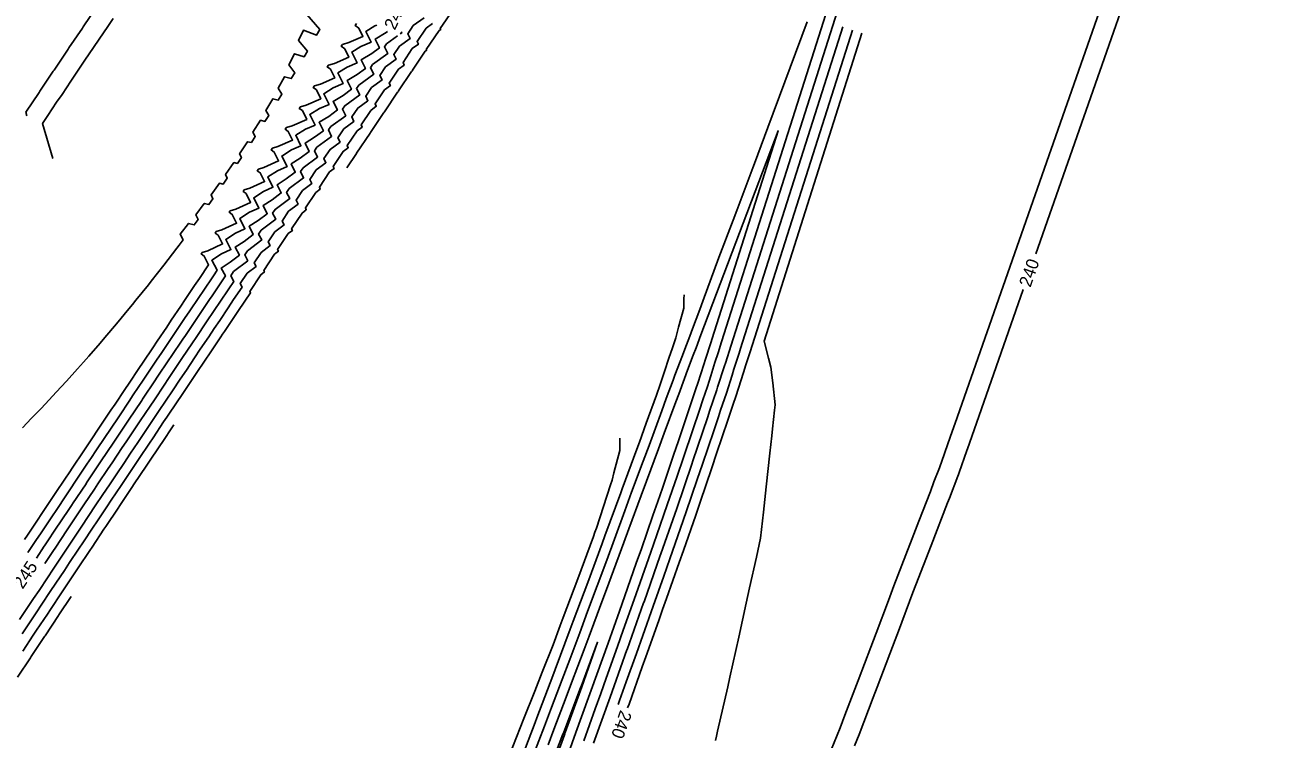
# Model space of a CAD drawing. Extents: x 1160447 to 1162032, y 616022 to 618272.
# Drawn here: x 1160773.9 to 1161021.2, y 616418.1 to 616560 of the extents above; entities that cross this region are included whole.
import ezdxf

# ---------------------------------------------------------------- set-up
doc = ezdxf.new("R2010")
doc.units = 0
doc.layers.add('D_Contours_Major', color=7, linetype='Continuous')
doc.layers.add('D_Contours_Minor', color=7, linetype='Continuous')

msp = doc.modelspace()

# ---------------------------------------------------------------- linework, layer by layer
at = {"layer": 'D_Contours_Major'}
for points in [[(1160974.68, 616514.45), (1161006.96, 616606.59), (1161007.29, 616607.53), (1161007.74, 616608.8), (1161010.59, 616616.88), (1161011.09, 616618.29), (1161013.25, 616624.34), (1161013.42, 616624.81), (1161013.92, 616626.21), (1161014.8, 616628.63), (1161017.28, 616635.52), (1161017.6, 616638.61), (1161019.75, 616644.29), (1161020.92, 616644.74), (1161021.22, 616647.76), (1161021.25, 616647.83)], [(1160893.59, 616424.24), (1160893.88, 616425.02), (1160896.51, 616432.4), (1160897.23, 616434.4), (1160899.8, 616441.64), (1160900.56, 616443.78), (1160901.33, 616445.98), (1160903.86, 616453.16), (1160904.68, 616455.52), (1160907.14, 616462.56), (1160908.01, 616465.1), (1160910.34, 616471.98), (1160911.29, 616474.8), (1160913.52, 616481.41), (1160914.59, 616484.59), (1160915.1, 616486.13), (1160915.62, 616487.76), (1160916.62, 616490.87), (1160917.11, 616492.4), (1160917.93, 616494.99), (1160938.26, 616558.94)], [(1160776.14, 616454.03), (1160777.71, 616456.4), (1160777.75, 616456.45), (1160780.47, 616460.54), (1160780.53, 616460.62), (1160783.23, 616464.67), (1160783.31, 616464.79), (1160786, 616468.8), (1160786.1, 616468.95), (1160788.76, 616472.94), (1160788.88, 616473.12), (1160791.52, 616477.07), (1160791.66, 616477.28), (1160794.29, 616481.2), (1160794.45, 616481.44), (1160797.06, 616485.33), (1160797.24, 616485.59), (1160799.83, 616489.46), (1160800.02, 616489.75), (1160802.6, 616493.59), (1160802.81, 616493.9), (1160805.37, 616497.71), (1160805.6, 616498.06), (1160808.14, 616501.84), (1160810.66, 616505.59), (1160810.91, 616505.96), (1160813.43, 616509.71), (1160813.69, 616510.09), (1160812.87, 616511.65), (1160814.66, 616512.82), (1160816.46, 616514.21), (1160815.65, 616515.8), (1160817.42, 616516.94), (1160819.24, 616518.33), (1160818.42, 616519.94), (1160820.19, 616521.07), (1160822.02, 616522.45), (1160821.2, 616524.08), (1160822.97, 616525.2), (1160824.8, 616526.57), (1160823.98, 616528.21), (1160825.77, 616529.34), (1160827.58, 616530.69), (1160826.76, 616532.35), (1160828.57, 616533.49), (1160830.36, 616534.81), (1160829.54, 616536.48), (1160831.39, 616537.64), (1160833.15, 616538.93), (1160832.32, 616540.62), (1160834.22, 616541.79), (1160835.93, 616543.05), (1160835.1, 616544.75), (1160837.06, 616545.95), (1160838.72, 616547.16), (1160837.88, 616548.88), (1160839.9, 616550.12), (1160841.51, 616551.28), (1160840.66, 616553), (1160842.76, 616554.29), (1160844.3, 616555.39), (1160843.45, 616557.13), (1160845.63, 616558.46), (1160845.92, 616558.67)], [(1160972.21, 616507.4), (1160962.44, 616479.52), (1160961.12, 616475.75), (1160960.99, 616475.39), (1160959.45, 616471.02), (1160959.32, 616470.65), (1160959.18, 616470.27), (1160957.53, 616465.95), (1160957.16, 616465), (1160953.91, 616456.55), (1160950.87, 616448.69), (1160950.28, 616447.17), (1160947.39, 616439.49), (1160946.74, 616437.75), (1160943.91, 616430.26), (1160943.18, 616428.34), (1160942.42, 616426.34), (1160939.6, 616418.94), (1160938.67, 616416.69)], [(1160772.37, 616430.33), (1160774.94, 616434.21), (1160775.11, 616434.46), (1160777.75, 616438.42), (1160777.86, 616438.59), (1160780.56, 616442.64), (1160780.61, 616442.72), (1160783.04, 616446.37)], [(1160877.31, 616409.96), (1160880.76, 616419.03), (1160880.85, 616419.24), (1160884.32, 616428.43), (1160884.35, 616428.53), (1160887.64, 616437.29), (1160884.49, 616428.47), (1160881.21, 616419.36), (1160881.13, 616419.13), (1160881.04, 616418.9), (1160877.74, 616409.8)]]:
    msp.add_lwpolyline(points, dxfattribs=at)
at = {"layer": 'D_Contours_Minor'}
for points in [[(1160886.82, 616417.23), (1160890.12, 616426.4), (1160890.92, 616428.63), (1160893.47, 616435.77), (1160893.5, 616435.86), (1160896.79, 616445.14), (1160896.87, 616445.35), (1160900.1, 616454.52), (1160900.21, 616454.85), (1160903.38, 616463.9), (1160906.35, 616472.66), (1160906.57, 616473.32), (1160909.46, 616481.87), (1160909.75, 616482.74), (1160909.9, 616483.19), (1160911.33, 616487.45), (1160911.49, 616487.97), (1160912.84, 616492.19), (1160913.02, 616492.75), (1160914.15, 616496.3), (1160954.95, 616624.67)], [(1160884.88, 616417.74), (1160887.16, 616424.08), (1160888.25, 616427.09), (1160889.35, 616430.19), (1160891.59, 616436.45), (1160892.73, 616439.68), (1160894.91, 616445.82), (1160896.09, 616449.17), (1160898.21, 616455.19), (1160899.43, 616458.67), (1160901.49, 616464.57), (1160903.43, 616470.29), (1160904.69, 616473.98), (1160906.55, 616479.5), (1160907.86, 616483.4), (1160908.54, 616485.43), (1160909.44, 616488.11), (1160910.12, 616490.22), (1160910.95, 616492.85), (1160911.57, 616494.78), (1160912.26, 616496.96), (1160947.99, 616609.37)], [(1160932.83, 616413.03), (1160935.84, 616420.31), (1160936.78, 616422.79), (1160939.42, 616429.7), (1160941.94, 616436.35), (1160942.98, 616439.1), (1160945.41, 616445.57), (1160946.51, 616448.51), (1160948.9, 616454.68), (1160950.14, 616457.89), (1160951.47, 616461.34), (1160953.75, 616467.27), (1160954.47, 616469.14), (1160955.55, 616471.97), (1160956.53, 616474.77), (1160957.22, 616476.71), (1160958.07, 616479.15), (1160958.66, 616480.83), (1161003.19, 616607.91)], [(1160853.17, 616561.34), (1160851.02, 616559.81), (1160849.92, 616558.18), (1160850.38, 616557.24), (1160848.26, 616555.71), (1160847.14, 616554.05), (1160847.6, 616553.13), (1160845.51, 616551.62), (1160844.36, 616549.92), (1160844.81, 616549.02), (1160842.75, 616547.53), (1160841.59, 616545.79), (1160842.02, 616544.9), (1160839.99, 616543.43), (1160838.81, 616541.67), (1160839.24, 616540.79), (1160837.24, 616539.33), (1160836.04, 616537.53), (1160836.46, 616536.68), (1160834.49, 616535.23), (1160833.26, 616533.4), (1160833.67, 616532.57), (1160831.74, 616531.14), (1160830.49, 616529.26), (1160830.89, 616528.45), (1160829, 616527.04), (1160827.72, 616525.12), (1160828.12, 616524.34), (1160826.25, 616522.94), (1160824.95, 616520.98), (1160825.34, 616520.22), (1160823.51, 616518.84), (1160822.18, 616516.84), (1160822.56, 616516.1), (1160820.77, 616514.73), (1160819.42, 616512.7), (1160819.79, 616511.98), (1160818.03, 616510.63), (1160816.65, 616508.56), (1160817.01, 616507.86), (1160815.33, 616505.37), (1160814.24, 616503.74), (1160812.56, 616501.24), (1160811.47, 616499.62), (1160810.38, 616497.99), (1160808.7, 616495.5), (1160807.55, 616493.79), (1160805.93, 616491.38), (1160804.73, 616489.59), (1160803.17, 616487.25), (1160801.91, 616485.39), (1160800.4, 616483.13), (1160799.1, 616481.19), (1160797.63, 616479), (1160796.29, 616476.99), (1160794.87, 616474.88), (1160793.48, 616472.8), (1160792.11, 616470.75), (1160790.67, 616468.59), (1160789.35, 616466.62), (1160787.85, 616464.38), (1160786.59, 616462.49), (1160785.05, 616460.18), (1160783.83, 616458.36), (1160782.25, 616455.99), (1160781.07, 616454.23), (1160779.45, 616451.8), (1160778.32, 616450.1), (1160776.66, 616447.61), (1160775.56, 616445.96), (1160773.87, 616443.42), (1160772.81, 616441.83)], [(1160773.35, 616479.88), (1160775.2, 616481.79), (1160777.08, 616483.77), (1160778.68, 616485.47), (1160780.1, 616487.01), (1160782.11, 616489.19), (1160784.29, 616491.62), (1160785.48, 616492.95), (1160786.54, 616494.17), (1160788.79, 616496.74), (1160789.71, 616497.82), (1160792.05, 616500.56), (1160794.51, 616503.54), (1160795.25, 616504.42), (1160795.92, 616505.26), (1160798.39, 616508.32), (1160798.97, 616509.06), (1160801.48, 616512.25), (1160804.05, 616515.62), (1160804.51, 616516.22), (1160805.3, 616517.28), (1160804.68, 616518.36), (1160806.37, 616520.51), (1160807.49, 616520.22), (1160808.28, 616521.32), (1160807.79, 616522.24), (1160809.48, 616524.49), (1160810.41, 616524.26), (1160811.21, 616525.39), (1160810.84, 616526.17), (1160812.5, 616528.5), (1160813.28, 616528.34), (1160814.07, 616529.5), (1160813.74, 616530.22), (1160815.37, 616532.59), (1160816.09, 616532.45), (1160816.87, 616533.63), (1160816.52, 616534.37), (1160818.1, 616536.75), (1160818.85, 616536.6), (1160819.61, 616537.79), (1160819.17, 616538.63), (1160820.67, 616541), (1160821.55, 616540.79), (1160822.29, 616541.98), (1160821.73, 616542.95), (1160823.14, 616545.29), (1160824.2, 616545.02), (1160824.92, 616546.2), (1160824.15, 616547.4), (1160825.44, 616549.67), (1160826.79, 616549.28), (1160827.48, 616550.45), (1160826.31, 616552.05), (1160827.45, 616554.21), (1160829.33, 616553.58), (1160829.99, 616554.73), (1160828.24, 616556.89), (1160829.2, 616558.88), (1160831.81, 616557.92), (1160832.43, 616559.04), (1160829.86, 616562)], [(1160788.11, 616563.48), (1160785.44, 616559.57), (1160785.27, 616559.33), (1160782.61, 616555.4), (1160782.45, 616555.16), (1160782.29, 616554.92), (1160779.64, 616550.99), (1160779.48, 616550.74), (1160776.84, 616546.81), (1160776.67, 616546.55), (1160774.06, 616542.62), (1160774.26, 616541.91)], [(1160837.81, 616531.54), (1160839.72, 616534.4), (1160839.76, 616534.43), (1160839.75, 616534.45), (1160842.44, 616538.47), (1160842.54, 616538.54), (1160842.52, 616538.58), (1160845.18, 616542.54), (1160845.32, 616542.65), (1160845.29, 616542.71), (1160847.91, 616546.61), (1160848.11, 616546.75), (1160848.07, 616546.84), (1160850.65, 616550.69), (1160850.89, 616550.86), (1160850.84, 616550.97), (1160853.39, 616554.76), (1160853.68, 616554.97), (1160853.61, 616555.09), (1160856.13, 616558.83), (1160856.46, 616559.07), (1160856.39, 616559.22), (1160858.88, 616562.91)], [(1160773.3, 616438.96), (1160774.49, 616440.75), (1160776.1, 616443.16), (1160777.25, 616444.88), (1160778.9, 616447.36), (1160780, 616449.01), (1160781.7, 616451.56), (1160782.75, 616453.14), (1160784.5, 616455.76), (1160785.51, 616457.27), (1160787.3, 616459.96), (1160788.27, 616461.4), (1160790.12, 616464.17), (1160791.02, 616465.53), (1160792.95, 616468.41), (1160793.78, 616469.66), (1160795.78, 616472.64), (1160796.55, 616473.78), (1160798.6, 616476.85), (1160799.31, 616477.91), (1160801.42, 616481.07), (1160802.07, 616482.03), (1160804.25, 616485.29), (1160804.84, 616486.15), (1160807.09, 616489.51), (1160807.6, 616490.28), (1160809.92, 616493.73), (1160810.37, 616494.4), (1160812.76, 616497.96), (1160813.14, 616498.52), (1160813.51, 616499.07), (1160815.91, 616502.64), (1160816.28, 616503.2), (1160818.68, 616506.75), (1160818.54, 616507.01), (1160820.75, 616510.33), (1160821.45, 616510.87), (1160821.3, 616511.16), (1160823.47, 616514.41), (1160824.22, 616514.99), (1160824.06, 616515.3), (1160826.19, 616518.49), (1160827, 616519.1), (1160826.83, 616519.44), (1160828.92, 616522.57), (1160829.77, 616523.22), (1160829.59, 616523.58), (1160831.64, 616526.65), (1160832.55, 616527.33), (1160832.36, 616527.72), (1160834.37, 616530.74), (1160835.33, 616531.44), (1160835.13, 616531.85), (1160837.1, 616534.82), (1160838.11, 616535.55), (1160837.9, 616535.99), (1160839.84, 616538.9), (1160840.89, 616539.67), (1160840.67, 616540.12), (1160842.59, 616542.98), (1160843.67, 616543.78), (1160843.44, 616544.25), (1160845.33, 616547.07), (1160846.46, 616547.89), (1160846.22, 616548.38), (1160848.08, 616551.15), (1160849.24, 616551.99), (1160848.99, 616552.51), (1160850.83, 616555.24), (1160852.03, 616556.1), (1160851.77, 616556.64), (1160853.58, 616559.32), (1160854.82, 616560.21)], [(1160839.75, 616560.21), (1160839.49, 616559.83), (1160840.19, 616559.31), (1160841, 616557.66), (1160838.24, 616556.46), (1160836.96, 616556.09), (1160836.71, 616555.72), (1160837.39, 616555.22), (1160838.21, 616553.54), (1160835.4, 616552.32), (1160834.17, 616551.96), (1160833.93, 616551.6), (1160834.58, 616551.13), (1160835.42, 616549.42), (1160832.57, 616548.18), (1160831.39, 616547.83), (1160831.15, 616547.49), (1160831.78, 616547.03), (1160832.63, 616545.3), (1160829.74, 616544.04), (1160828.6, 616543.7), (1160828.37, 616543.37), (1160828.98, 616542.92), (1160829.84, 616541.18), (1160826.93, 616539.9), (1160825.81, 616539.57), (1160825.59, 616539.24), (1160826.19, 616538.81), (1160827.05, 616537.06), (1160824.12, 616535.77), (1160823.02, 616535.44), (1160822.81, 616535.12), (1160823.39, 616534.69), (1160824.27, 616532.93), (1160821.32, 616531.63), (1160820.24, 616531.3), (1160820.03, 616530.99), (1160820.61, 616530.57), (1160821.49, 616528.81), (1160818.53, 616527.49), (1160817.45, 616527.17), (1160817.24, 616526.86), (1160817.82, 616526.44), (1160818.7, 616524.69), (1160815.75, 616523.36), (1160814.66, 616523.03), (1160814.45, 616522.72), (1160815.04, 616522.3), (1160815.92, 616520.56), (1160812.97, 616519.23), (1160811.88, 616518.89), (1160811.67, 616518.58), (1160812.26, 616518.16), (1160813.14, 616516.44), (1160810.21, 616515.1), (1160809.09, 616514.75), (1160808.88, 616514.44), (1160809.48, 616514.01), (1160810.36, 616512.31), (1160808.52, 616509.56), (1160807.58, 616508.18), (1160805.73, 616505.42), (1160804.81, 616504.05), (1160802.94, 616501.27), (1160802.03, 616499.92), (1160800.14, 616497.11), (1160799.26, 616495.79), (1160797.35, 616492.95), (1160796.49, 616491.66), (1160794.56, 616488.78), (1160793.72, 616487.53), (1160791.76, 616484.61), (1160790.95, 616483.39), (1160790.14, 616482.2), (1160788.18, 616479.26), (1160787.4, 616478.1), (1160785.41, 616475.12), (1160783.37, 616472.07), (1160782.64, 616470.99), (1160781.93, 616469.92), (1160779.88, 616466.85), (1160777.77, 616463.69), (1160777.12, 616462.71), (1160776.48, 616461.76), (1160774.35, 616458.57), (1160773.76, 616457.68)], [(1160843.77, 616559.92), (1160843.37, 616559.75), (1160841.6, 616558.67), (1160842.65, 616556.52), (1160840.62, 616555.65), (1160838.81, 616554.55), (1160839.86, 616552.41), (1160837.87, 616551.55), (1160836.03, 616550.42), (1160837.07, 616548.29), (1160835.12, 616547.44), (1160833.24, 616546.29), (1160834.28, 616544.17), (1160832.36, 616543.34), (1160830.46, 616542.16), (1160831.5, 616540.05), (1160829.6, 616539.22), (1160827.67, 616538.03), (1160828.71, 616535.93), (1160826.83, 616535.11), (1160824.89, 616533.89), (1160825.93, 616531.81), (1160824.06, 616530.99), (1160822.11, 616529.76), (1160823.14, 616527.69), (1160821.28, 616526.86), (1160819.33, 616525.62), (1160820.36, 616523.57), (1160818.49, 616522.73), (1160816.54, 616521.48), (1160817.58, 616519.45), (1160815.7, 616518.59), (1160813.76, 616517.34), (1160814.8, 616515.32), (1160812.91, 616514.46), (1160810.98, 616513.2), (1160812.03, 616511.2), (1160811.3, 616510.12), (1160809.25, 616507.07), (1160808.52, 616505.98), (1160806.47, 616502.94), (1160805.73, 616501.83), (1160803.7, 616498.82), (1160802.94, 616497.68), (1160800.93, 616494.69), (1160800.15, 616493.52), (1160798.16, 616490.56), (1160797.35, 616489.36), (1160795.39, 616486.43), (1160794.56, 616485.2), (1160792.62, 616482.3), (1160790.71, 616479.45), (1160789.85, 616478.16), (1160787.98, 616475.36), (1160787.09, 616474.03), (1160786.17, 616472.67), (1160784.32, 616469.9), (1160782.51, 616467.19), (1160781.56, 616465.76), (1160780.58, 616464.29), (1160778.79, 616461.62), (1160777.06, 616459.03), (1160776.03, 616457.49), (1160774.47, 616455.14)], [(1160791.42, 616561.24), (1160790.33, 616559.65), (1160788.58, 616557.09), (1160787.48, 616555.45), (1160785.77, 616552.92), (1160784.06, 616550.39), (1160782.96, 616548.75), (1160781.23, 616546.16), (1160780.16, 616544.58), (1160778.41, 616541.94), (1160777.38, 616540.39), (1160779.41, 616533.44)], [(1160929.29, 616560.55), (1160921.49, 616539.57), (1160918.8, 616532.44), (1160918.48, 616531.58), (1160915.27, 616523.08), (1160914.57, 616521.19), (1160911.75, 616513.71), (1160908.56, 616505.06), (1160908.29, 616504.33), (1160908.15, 616503.97), (1160906.29, 616499.04), (1160906.14, 616498.66), (1160904.76, 616495.01), (1160904.49, 616494.29), (1160903, 616490.37), (1160902.63, 616489.38), (1160901.29, 616485.71), (1160900.4, 616483.3), (1160897.86, 616476.4), (1160896.7, 616473.28), (1160894.4, 616467.1), (1160893.04, 616463.39), (1160890.99, 616457.79), (1160889.45, 616453.62), (1160887.55, 616448.49), (1160885.65, 616443.39), (1160884.08, 616439.19), (1160882.09, 616433.87), (1160880.6, 616429.91), (1160878.5, 616424.34), (1160877.09, 616420.63), (1160874.87, 616414.79)], [(1160891.71, 616424.91), (1160892, 616425.71), (1160893.33, 616429.42), (1160895.35, 616435.08), (1160896.61, 616438.65), (1160898.67, 616444.46), (1160900.79, 616450.45), (1160901.98, 616453.84), (1160904.13, 616459.99), (1160905.26, 616463.23), (1160907.43, 616469.63), (1160908.46, 616472.65), (1160910.71, 616479.32), (1160911.64, 616482.08), (1160912.08, 616483.4), (1160913.22, 616486.79), (1160914.36, 616490.37), (1160914.73, 616491.53), (1160915.76, 616494.76), (1160916.04, 616495.65), (1160936.35, 616559.55)], [(1160847.88, 616557.76), (1160845.7, 616556.19), (1160845.3, 616555.59), (1160845.95, 616554.26), (1160842.93, 616552.09), (1160842.51, 616551.46), (1160843.16, 616550.15), (1160840.17, 616547.98), (1160839.73, 616547.34), (1160840.37, 616546.03), (1160837.4, 616543.88), (1160836.95, 616543.21), (1160837.59, 616541.92), (1160834.64, 616539.76), (1160834.18, 616539.08), (1160834.8, 616537.8), (1160831.88, 616535.65), (1160831.4, 616534.94), (1160832.02, 616533.69), (1160829.11, 616531.54), (1160828.62, 616530.8), (1160829.24, 616529.57), (1160826.35, 616527.42), (1160825.85, 616526.67), (1160826.46, 616525.45), (1160823.59, 616523.3), (1160823.08, 616522.53), (1160823.68, 616521.34), (1160820.83, 616519.18), (1160820.3, 616518.39), (1160820.9, 616517.22), (1160818.07, 616515.05), (1160817.53, 616514.25), (1160818.13, 616513.1), (1160815.31, 616510.93), (1160814.76, 616510.11), (1160815.35, 616508.98), (1160814.38, 616507.54), (1160812.58, 616504.85), (1160811.61, 616503.42), (1160809.81, 616500.73), (1160807.99, 616498.03), (1160807.03, 616496.61), (1160805.18, 616493.85), (1160804.26, 616492.48), (1160802.38, 616489.67), (1160801.5, 616488.36), (1160799.58, 616485.49), (1160798.73, 616484.23), (1160796.77, 616481.31), (1160795.96, 616480.1), (1160793.98, 616477.14), (1160793.2, 616475.97), (1160791.18, 616472.96), (1160790.43, 616471.84), (1160788.38, 616468.77), (1160787.67, 616467.71), (1160785.58, 616464.58), (1160784.91, 616463.58), (1160782.79, 616460.4), (1160782.15, 616459.45), (1160780, 616456.22), (1160779.39, 616455.32), (1160777.8, 616452.93)], [(1160848.64, 616558.58), (1160848.74, 616558.37), (1160848.44, 616558.16)], [(1160940.16, 616558.33), (1160920.71, 616497.14), (1160921.61, 616493.71), (1160922.08, 616491.94), (1160922.43, 616488.85), (1160922.92, 616484.47), (1160922.81, 616483.43), (1160922.41, 616479.73), (1160922.26, 616478.34), (1160921.88, 616474.86), (1160921.14, 616468.16), (1160920.59, 616463.17), (1160920, 616457.97), (1160919.18, 616454.19), (1160917.85, 616448.13), (1160917.18, 616445.08), (1160915.68, 616438.3), (1160913.89, 616430.33), (1160913.48, 616428.47), (1160911.48, 616419.64), (1160911.25, 616418.64), (1160911.06, 616417.79)], [(1160881.78, 616415.08), (1160883, 616418.44), (1160884.18, 616421.72), (1160886.37, 616427.78), (1160888.59, 616434.01), (1160889.71, 616437.14), (1160891.97, 616443.49), (1160893.03, 616446.5), (1160895.32, 616452.98), (1160896.33, 616455.87), (1160898.64, 616462.48), (1160899.61, 616465.25), (1160900.52, 616467.93), (1160902.8, 616474.65), (1160903.64, 616477.12), (1160905.98, 616484.07), (1160907.18, 616487.66), (1160907.55, 616488.77), (1160908.74, 616492.48), (1160909.06, 616493.51), (1160910.12, 616496.82), (1160910.37, 616497.62), (1160923.5, 616538.93), (1160908.18, 616498.38), (1160907.19, 616495.77), (1160906.65, 616494.35), (1160905.5, 616491.33), (1160904.89, 616489.71), (1160903.75, 616486.61), (1160903.18, 616485.05), (1160900.88, 616478.83), (1160899.74, 616475.74), (1160897.36, 616469.32), (1160896.29, 616466.43), (1160893.85, 616459.8), (1160892.87, 616457.12), (1160890.36, 616450.32), (1160889.43, 616447.81), (1160888.5, 616445.31), (1160885.96, 616438.51), (1160884.97, 616435.85), (1160882.48, 616429.22), (1160881.41, 616426.38), (1160878.97, 616419.93), (1160877.82, 616416.91)], [(1160871.93, 616412.67), (1160875.22, 616421.32), (1160875.59, 616422.29), (1160878.72, 616430.6), (1160879.21, 616431.89), (1160882.21, 616439.88), (1160882.8, 616441.48), (1160885.67, 616449.17), (1160888.53, 616456.93), (1160889.1, 616458.47), (1160892.23, 616466.98), (1160892.52, 616467.78), (1160895.46, 616475.68), (1160895.96, 616477.08), (1160897.31, 616480.83), (1160899.31, 616486.41), (1160900.05, 616488.49), (1160900.9, 616491.1), (1160901.8, 616493.76), (1160902.49, 616495.8), (1160903.16, 616497.8), (1160903.73, 616499.92), (1160904.74, 616503.68), (1160904.76, 616505.56), (1160904.84, 616506.32)], [(1160773.43, 616435.54), (1160775.53, 616438.69), (1160776.18, 616439.67), (1160778.33, 616442.9), (1160778.93, 616443.8), (1160781.13, 616447.11), (1160781.68, 616447.93), (1160783.94, 616451.32), (1160784.43, 616452.06), (1160786.75, 616455.53), (1160787.19, 616456.19), (1160789.56, 616459.74), (1160789.94, 616460.31), (1160792.39, 616463.97), (1160792.7, 616464.44), (1160795.23, 616468.23), (1160795.46, 616468.56), (1160798.08, 616472.48), (1160798.22, 616472.69), (1160800.91, 616476.71), (1160800.98, 616476.81), (1160803.45, 616480.5)], [(1160892.07, 616477.87), (1160892.07, 616477.7), (1160892.05, 616475.4), (1160890.88, 616470.93), (1160890.5, 616469.48), (1160890.21, 616468.6), (1160887.39, 616459.96), (1160887.11, 616459.18), (1160886.8, 616458.32), (1160883.72, 616449.87), (1160880.83, 616442.19), (1160880.23, 616440.6), (1160878.79, 616436.8), (1160876.65, 616431.36), (1160875.16, 616427.6), (1160873.01, 616422.14), (1160870.04, 616414.7), (1160869.28, 616412.96), (1160867.34, 616408.5), (1160865.32, 616403.86), (1160864.54, 616402.08), (1160863.48, 616400.28), (1160861.91, 616397.63)]]:
    msp.add_lwpolyline(points, dxfattribs=at)

# ---------------------------------------------------------------- texts
at = {"layer": 'D_Contours_Major'}
for s, rotation, p in [('245', 65.0096, (1160847.36, 616558.78)), ('240', 70.6911, (1160973.63, 616507.68)), ('245', 56.3165, (1160773.42, 616447.72)), ('240', 250.1955, (1160892.17, 616423.96))]:
    msp.add_text(s, height=2.49, rotation=rotation, dxfattribs=at).set_placement(p)

doc.saveas('drawing.dxf')
